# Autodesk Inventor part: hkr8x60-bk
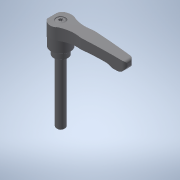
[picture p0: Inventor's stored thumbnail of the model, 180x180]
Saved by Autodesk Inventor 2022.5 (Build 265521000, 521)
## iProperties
Created: 2017-09
Part Number: hkr8x60-bk
Material: 一般
Document SubType Name: Modeling
Designer: imaocorp
Density: 1 g/cm^3
Appearance: 既定
Author: imaocorp
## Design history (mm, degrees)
node "hkr8x60-bk.x_t1"
node "hkr8x60-bk"
node "Base1"
